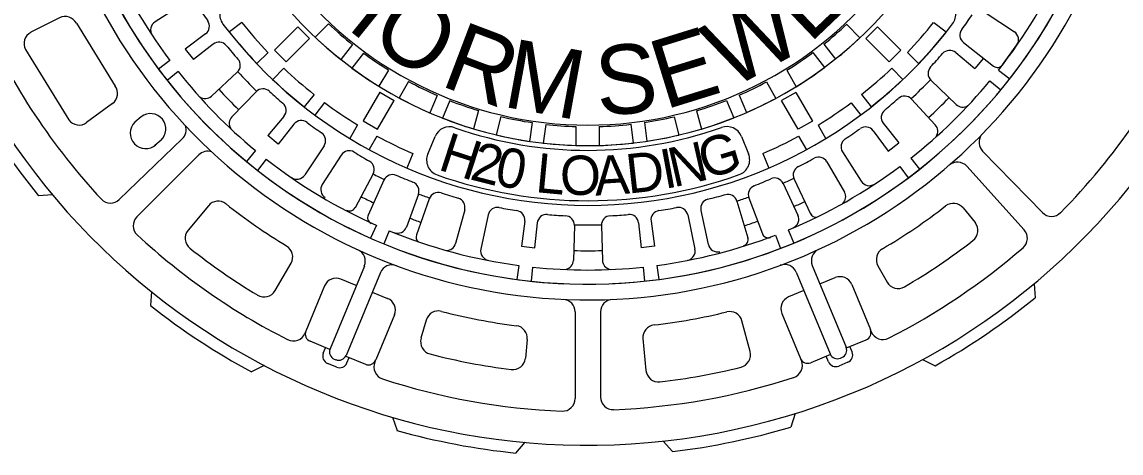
# Model space of a CAD drawing. Extents: x -7.1 to 10, y -5 to 6.
# Drawn here: x -5.508 to -3.691, y -0.443 to 0.27 of the extents above; entities that cross this region are included whole.
import ezdxf

# ---------------------------------------------------------------- set-up
doc = ezdxf.new("R2010")
doc.units = 0
doc.layers.add('Level 1', color=7, linetype='Continuous')

# ---------------------------------------------------------------- blocks, each defined once
blk = doc.blocks.new('CRAN')
at = {"layer": 'Level 1'}
for p, q in [((-3.652, 6.599), (-1.391, 7.083)), ((-3.232, 4.178), (-1.568, 4.4)), ((-1.568, 4.4), (-1.47, 3.52)), ((-3.114, 3.352), (-1.47, 3.52)), ((-2.949, 0.9), (-0.638, 0.965)), ((-2.949, -0.892), (-0.638, -0.957)), ((-3.114, -3.345), (-1.471, -3.52)), ((-1.568, -4.392), (-1.47, -3.512)), ((-3.232, -4.17), (-1.568, -4.392)), ((-3.652, -6.592), (-1.391, -7.076))]:
    blk.add_line(p, q, dxfattribs=at)
for centre, radius, start, end in [((-3.521, 5.988), 0.625, 102.07218, 190.93682), ((-1.26, 6.472), 0.625, 11.01435, 102.07218), ((-34.491, 0.004), 30.918, 8.74094, 10.93682), ((-3.315, 4.797), 0.625, 188.74094, 277.60558), ((-3.048, 2.731), 0.625, 96.07758, 184.94222), ((-34.473, 0.013), 30.918, 2.74634, 4.94222), ((-2.967, 1.524), 0.625, 182.74634, 271.61098), ((-0.656, 1.589), 0.625, 271.61098, 348.82418), ((-2.967, -1.517), 0.625, 88.38902, 177.25366), ((-0.656, -1.582), 0.625, 11.17582, 88.38902), ((-34.473, -0.006), 30.918, 355.05778, 357.25366), ((-3.048, -2.723), 0.625, 175.05778, 263.92242), ((-3.315, -4.79), 0.625, 82.39442, 171.25906), ((-34.491, 0.004), 30.918, 349.06318, 351.25906), ((-3.521, -5.981), 0.625, 169.06318, 257.92782), ((-1.26, -6.464), 0.625, 257.92782, 348.98565)]:
    blk.add_arc(centre, radius, start, end, dxfattribs=at)

msp = doc.modelspace()

# ---------------------------------------------------------------- linework, layer by layer
at = {"layer": 'Level 1'}
for p, q in [((-5.4455, 0.2769), (-5.4929, 0.2529)), ((-3.9159, 0.2859), (-3.8677, 0.2539)), ((-5.4177, 0.2681), (-5.3534, 0.164)), ((-5.1443, 0.2694), (-5.1649, 0.2535)), ((-5.0517, 0.2621), (-5.0903, 0.2235)), ((-5.0517, 0.2621), (-5.0323, 0.2428)), ((-5.001, 0.2668), (-5.0231, 0.2447)), ((-4.1447, 0.2661), (-4.1228, 0.2438)), ((-4.0936, 0.2621), (-4.113, 0.2428)), ((-4.0936, 0.2621), (-4.055, 0.2235)), ((-4.001, 0.2694), (-3.9804, 0.2535)), ((-5.071, 0.2041), (-5.0323, 0.2428)), ((-4.0743, 0.2041), (-4.113, 0.2428)), ((-5.5019, 0.2245), (-5.4301, 0.1082)), ((-5.101, 0.2196), (-5.1194, 0.2011)), ((-5.0903, 0.2235), (-5.071, 0.2041)), ((-4.9613, 0.2325), (-4.9804, 0.2077)), ((-4.9433, 0.2187), (-4.9624, 0.1939)), ((-4.2005, 0.2195), (-4.1815, 0.1947)), ((-4.1825, 0.2334), (-4.1635, 0.2086)), ((-4.055, 0.2235), (-4.0743, 0.2041)), ((-4.0443, 0.2196), (-4.0259, 0.2011)), ((-3.9645, 0.2195), (-3.9328, 0.1931)), ((-3.9518, 0.2361), (-3.9019, 0.197)), ((-3.8872, 0.1989), (-3.8635, 0.232)), ((-5.2633, 0.2062), (-5.2821, 0.1922)), ((-3.9188, 0.2102), (-3.9328, 0.1931)), ((-5.2493, 0.188), (-5.2677, 0.1735)), ((-5.0749, 0.1934), (-5.0933, 0.175)), ((-4.9019, 0.1906), (-4.9178, 0.1637)), ((-4.2439, 0.1901), (-4.2283, 0.163)), ((-4.0704, 0.1934), (-4.052, 0.175)), ((-3.8937, 0.1904), (-3.8753, 0.176)), ((-4.8686, 0.1714), (-4.8843, 0.1443)), ((-4.2772, 0.1709), (-4.2618, 0.1437)), ((-4.0055, 0.1737), (-3.9639, 0.1336)), ((-3.9082, 0.1725), (-3.8901, 0.1576)), ((-5.025, 0.1502), (-5.041, 0.1296)), ((-4.9164, 0.1538), (-4.9437, 0.1064)), ((-4.9164, 0.1538), (-4.8927, 0.1401)), ((-4.8214, 0.1485), (-4.8335, 0.1197)), ((-4.3222, 0.1491), (-4.3103, 0.1202)), ((-4.2287, 0.1535), (-4.2524, 0.1399)), ((-4.2287, 0.1535), (-4.2014, 0.1062)), ((-4.1203, 0.1502), (-4.1043, 0.1296)), ((-5.358, 0.1352), (-5.4007, 0.1036)), ((-5.0077, 0.1368), (-5.0235, 0.1161)), ((-4.92, 0.0927), (-4.8927, 0.1401)), ((-4.8005, 0.1399), (-4.8125, 0.111)), ((-4.3431, 0.1404), (-4.3313, 0.1115)), ((-4.2251, 0.0925), (-4.2524, 0.1399)), ((-4.1374, 0.1365), (-4.1216, 0.1158)), ((-4.0375, 0.1424), (-3.9983, 0.1)), ((-5.3107, 0.1133), (-5.3212, 0.1043)), ((-4.7532, 0.1235), (-4.7616, 0.0934)), ((-4.7161, 0.1135), (-4.7242, 0.0833)), ((-4.4298, 0.1133), (-4.422, 0.083)), ((-4.3927, 0.1232), (-4.3847, 0.093)), ((-4.9531, 0.0999), (-4.966, 0.0773)), ((-4.9437, 0.1064), (-4.92, 0.0927)), ((-4.6646, 0.1036), (-4.6688, 0.0726)), ((-4.6421, 0.1007), (-4.6462, 0.0697)), ((-4.5922, 0.0971), (-4.5925, 0.0658)), ((-4.5537, 0.0971), (-4.5538, 0.0658)), ((-4.5014, 0.1008), (-4.4975, 0.0698)), ((-4.479, 0.1038), (-4.4749, 0.0728)), ((-4.2014, 0.1062), (-4.2251, 0.0925)), ((-4.1921, 0.0996), (-4.1791, 0.077)), ((-4.0843, 0.1025), (-4.0587, 0.0701)), ((-5.2427, 0.0766), (-5.3468, -0.0238)), ((-5.2774, 0.0748), (-5.2879, 0.0658)), ((-4.921, 0.0814), (-4.9341, 0.0589)), ((-4.837, 0.0516), (-4.825, 0.0806)), ((-4.3187, 0.0809), (-4.3069, 0.0519)), ((-4.2242, 0.0811), (-4.2111, 0.0586)), ((-4.1011, 0.0902), (-4.076, 0.0566)), ((-5.1217, 0.0574), (-5.1367, 0.0394)), ((-4.1517, 0.0554), (-4.1209, 0.0065)), ((-4.076, 0.0566), (-4.0585, 0.0702)), ((-3.8212, -0.0452), (-3.9202, 0.0565)), ((-5.2154, 0.0501), (-5.3177, -0.0522)), ((-5.1038, 0.043), (-5.1183, 0.0246)), ((-4.9801, 0.0499), (-5.0114, 0.0014)), ((-4.8617, 0.0525), (-4.8717, 0.0285)), ((-4.2835, 0.0523), (-4.2735, 0.0283)), ((-4.1773, 0.0388), (-4.1485, -0.0113)), ((-4.0387, 0.045), (-4.0242, 0.0266)), ((-4.9271, 0.0187), (-4.9572, -0.0371)), ((-4.0569, 0.031), (-4.0429, 0.0122)), ((-3.9461, 0.0314), (-3.8514, -0.0736)), ((-4.9094, 0.0085), (-4.9356, -0.0492)), ((-4.2497, 0.003), (-4.2253, -0.0494)), ((-4.2317, 0.0102), (-4.2045, -0.047)), ((-5.4571, -0.0156), (-5.4804, -0.0173)), ((-4.8525, -0.0147), (-4.8723, -0.0691)), ((-5.1994, -0.0338), (-5.2332, -0.0745)), ((-4.8347, -0.0223), (-4.8558, -0.082)), ((-4.3261, -0.0261), (-4.3079, -0.0868)), ((-4.3064, -0.0208), (-4.2841, -0.0802)), ((-4.776, -0.0406), (-4.791, -0.0964)), ((-4.3856, -0.0415), (-4.3734, -0.098)), ((-3.9524, -0.0376), (-3.9326, -0.0618)), ((-4.922, -0.0662), (-4.9315, -0.0876)), ((-4.9009, -0.0752), (-4.9098, -0.0969)), ((-4.2625, -0.0825), (-4.2541, -0.1044)), ((-4.2412, -0.074), (-4.2322, -0.0956)), ((-5.0893, -0.1743), (-5.063, -0.1287)), ((-4.9418, -0.1336), (-4.9985, -0.2705)), ((-4.9153, -0.1445), (-4.9721, -0.2814)), ((-4.6866, -0.1326), (-4.6897, -0.1559)), ((-4.6638, -0.1354), (-4.6662, -0.1587)), ((-4.4812, -0.1354), (-4.4787, -0.1587)), ((-4.4584, -0.1326), (-4.4553, -0.1559)), ((-4.228, -0.1439), (-4.172, -0.279)), ((-4.2016, -0.1329), (-4.1456, -0.268)), ((-4.0932, -0.1331), (-4.078, -0.1604)), ((-4.9551, -0.1657), (-4.9804, -0.1553)), ((-4.189, -0.1633), (-4.1637, -0.1528)), ((-3.8351, -0.1629), (-3.8334, -0.1861)), ((-5.2938, -0.1759), (-5.2953, -0.1991)), ((-5.0076, -0.1665), (-5.0385, -0.2411)), ((-4.9287, -0.1767), (-4.9034, -0.1871)), ((-4.2154, -0.1742), (-4.2407, -0.1847)), ((-4.1365, -0.1641), (-4.1056, -0.2386)), ((-4.8921, -0.2144), (-4.923, -0.2889)), ((-4.5933, -0.2096), (-4.5933, -0.3528)), ((-4.5517, -0.2096), (-4.5517, -0.3503)), ((-4.252, -0.2119), (-4.2211, -0.2865)), ((-4.8396, -0.223), (-4.8482, -0.2531)), ((-4.3042, -0.2752), (-4.3179, -0.2243)), ((-5.0385, -0.2411), (-5.04, -0.2447)), ((-4.4815, -0.2537), (-4.4766, -0.3063)), ((-4.1051, -0.2401), (-4.1042, -0.2423)), ((-4.999, -0.2716), (-5.0315, -0.2581)), ((-5.0096, -0.2777), (-5.0059, -0.2687)), ((-4.6725, -0.2551), (-4.6757, -0.2862)), ((-4.1451, -0.2691), (-4.1126, -0.2557)), ((-4.1356, -0.2757), (-4.1394, -0.2667)), ((-4.9903, -0.288), (-4.9903, -0.288)), ((-4.9725, -0.2825), (-4.94, -0.296)), ((-4.9705, -0.2939), (-4.9668, -0.2849)), ((-4.9237, -0.2904), (-4.9246, -0.2925)), ((-4.2211, -0.2865), (-4.2196, -0.2901)), ((-4.1716, -0.2801), (-4.2041, -0.2935)), ((-4.1748, -0.2919), (-4.1785, -0.2829)), ((-4.1538, -0.2855), (-4.1539, -0.2855)), ((-4.0192, -0.2882), (-3.9983, -0.2984)), ((-5.1076, -0.298), (-5.1284, -0.3085)), ((-4.9875, -0.301), (-5.0026, -0.2947)), ((-4.1427, -0.2927), (-4.1578, -0.299)), ((-4.2298, -0.3777), (-4.2371, -0.3999)), ((-4.8954, -0.3836), (-4.8878, -0.4056)), ((-4.6766, -0.4251), (-4.6918, -0.4429)), ((-4.4478, -0.4231), (-4.4324, -0.4405))]:
    msp.add_line(p, q, dxfattribs=at)
for centre, radius, start, end in [((-4.5726, 0.7218), 1.1516, 195.0717, 189.1227), ((-4.5725, 0.7218), 0.8854, 184.6051, 245.3048), ((-4.5725, 0.7218), 0.8854, 184.6051, 354.3326), ((-4.5725, 0.7218), 0.8854, 272.6352, 354.3326), ((-4.5725, 0.7218), 0.9115, 188.0305, 347.6848), ((-4.5725, 0.7218), 0.862, 202.6056, 216.7344), ((-4.5725, 0.7218), 0.862, 321.9456, 336.078), ((-4.5725, 0.7218), 0.6224, 216.9847, 323.0153), ((-4.5725, 0.7218), 0.6562, 217.1874, 322.8126), ((-5.1547, 0.2823), 0.026, 125, 217.0904), ((-3.9905, 0.2825), 0.026, 322.9239, 55), ((-5.4361, 0.2583), 0.0208, 28.0611, 116.8565), ((-4.5726, 0.722), 0.7729, 323.0809, 325.2768), ((-4.5712, 0.7239), 1.0983, 204.3143, 222.8654), ((-4.5726, 0.7224), 0.7557, 217.0904, 322.9239), ((-4.5725, 0.7219), 0.7292, 218.362, 223.5455), ((-4.5725, 0.7218), 0.625, 226.7203, 231.5279), ((-4.5725, 0.7218), 0.625, 308.6043, 313.1939), ((-4.5728, 0.7219), 0.7292, 316.4545, 321.638), ((-3.9422, 0.2484), 0.0156, 143.0809, 231.9456), ((-4.573, 0.7263), 1.0983, 315.3646, 335.5685), ((-5.4835, 0.2343), 0.0208, 116.8565, 207.9663), ((-4.5725, 0.7219), 0.7552, 218.3392, 223.6005), ((-4.5725, 0.7218), 0.6563, 226.6317, 231.5646), ((-4.5725, 0.7218), 0.6563, 308.552, 313.2544), ((-4.5728, 0.7219), 0.7552, 316.3995, 321.6608), ((-3.8763, 0.2409), 0.0156, 325.3544, 56.4122), ((-4.5725, 0.7218), 0.625, 233.6043, 238.1939), ((-4.5725, 0.7218), 0.625, 301.7203, 306.5279), ((-3.9745, 0.2075), 0.0156, 50.4176, 139.2822), ((-4.5722, 0.7219), 0.7729, 317.0863, 319.2822), ((-4.5725, 0.7218), 0.862, 218.262, 230.418), ((-4.5725, 0.7218), 0.7875, 222.7158, 225.9774), ((-4.5727, 0.7221), 0.7292, 226.4702, 231.6538), ((-4.5725, 0.7218), 0.6563, 233.552, 238.2544), ((-4.5725, 0.7218), 0.6563, 301.6317, 306.5646), ((-4.5726, 0.7221), 0.7292, 308.3462, 313.5298), ((-3.9946, 0.185), 0.0156, 137.0863, 225.951), ((-3.8955, 0.2052), 0.0104, 231.9456, 322.6551), ((-5.3704, 0.152), 0.0208, 306.5465, 35.3378), ((-4.5727, 0.7221), 0.7552, 226.4152, 231.6765), ((-4.5725, 0.7218), 0.625, 241.7203, 246.5279), ((-4.5725, 0.7218), 0.625, 293.6043, 298.1939), ((-4.5726, 0.7221), 0.7552, 308.3235, 313.5848), ((-4.5725, 0.7218), 0.862, 308.262, 320.418), ((-4.5725, 0.7218), 0.7875, 312.7158, 315.9774), ((-4.5725, 0.7211), 1.1703, 209.3462, 219.1251), ((-4.5725, 0.7218), 0.8301, 222.7192, 225.9733), ((-4.049, 0.1318), 0.0156, 42.729, 131.5937), ((-4.5726, 0.7219), 0.7292, 233.362, 238.5455), ((-4.5725, 0.7218), 0.6563, 241.6317, 246.5646), ((-4.5725, 0.7218), 0.625, 248.6043, 253.1939), ((-4.5725, 0.7218), 0.625, 286.7203, 291.5279), ((-4.5725, 0.7218), 0.6563, 293.552, 298.2544), ((-4.5721, 0.7219), 0.7292, 301.4147, 306.5983), ((-4.5725, 0.7216), 0.7729, 309.3978, 311.5937), ((-4.5725, 0.7218), 0.8301, 312.7192, 315.9733), ((-3.9531, 0.1448), 0.0156, 225.951, 303.1642), ((-5.2953, 0.093), 0.0255, 311.5699, 126.9738), ((-4.5725, 0.7218), 0.6563, 248.552, 253.2544), ((-4.5725, 0.7218), 0.625, 256.7203, 261.5279), ((-4.5725, 0.7218), 0.625, 278.6043, 283.1939), ((-4.5725, 0.7218), 0.6563, 286.6317, 291.5646), ((-4.072, 0.1122), 0.0156, 129.3978, 218.2624), ((-5.4131, 0.1203), 0.0208, 215.392, 306.5465), ((-5.3032, 0.0861), 0.0255, 134.687, 311.5622), ((-5.2571, 0.0916), 0.0208, 313.9401, 20.0195), ((-4.801, 0.0706), 0.026, 70.6644, 157.5067), ((-4.5725, 0.7218), 0.6641, 250.6644, 289.4373), ((-4.5725, 0.7218), 0.625, 263.6043, 268.1939), ((-4.5725, 0.7218), 0.625, 271.7203, 276.5279), ((-4.3428, 0.071), 0.026, 22.2988, 109.4373), ((-4.5726, 0.722), 0.7729, 303.4032, 305.5991), ((-4.1136, 0.0809), 0.0156, 36.7344, 125.5991), ((-4.0098, 0.0894), 0.0156, 325.5158, 42.729), ((-4.5727, 0.722), 0.7292, 241.4702, 246.6538), ((-4.5725, 0.7218), 0.6563, 256.6317, 261.5646), ((-4.5725, 0.7218), 0.6563, 278.552, 283.2544), ((-4.572, 0.722), 0.7292, 293.3065, 298.49), ((-4.1385, 0.0637), 0.0156, 123.4032, 212.2678), ((-3.9053, 0.0711), 0.0208, 145.8214, 224.2281), ((-5.2007, 0.0354), 0.0208, 71.0549, 135), ((-4.9669, 0.0415), 0.0156, 58.3474, 147.2121), ((-4.5531, 0.7127), 0.7729, 238.3474, 240.5433), ((-4.5725, 0.7218), 0.6563, 263.552, 268.2544), ((-4.5725, 0.7218), 0.6563, 271.6317, 276.5646), ((-4.5725, 0.7218), 0.862, 231.9456, 246.078), ((-4.9409, 0.0261), 0.0156, 331.6787, 60.5433), ((-4.813, 0.0417), 0.026, 157.5067, 250.5275), ((-4.331, 0.0421), 0.026, 289.5614, 22.2988), ((-4.5708, 0.722), 0.7729, 296.6109, 298.8068), ((-4.1909, 0.031), 0.0156, 29.9422, 118.8068), ((-3.9615, 0.0174), 0.0208, 42.022, 131.4737), ((-4.5725, 0.7218), 0.7875, 243.2323, 244.7184), ((-4.5725, 0.7218), 0.862, 292.6056, 306.7344), ((-4.2176, 0.017), 0.0156, 116.6109, 205.4756), ((-4.9982, -0.0071), 0.0156, 147.2121, 238.2699), ((-4.8952, 0.002), 0.0156, 66.704, 155.5686), ((-4.5833, 0.7263), 0.7729, 246.704, 248.8998), ((-4.8672, -0.0094), 0.0156, 340.0352, 68.8998), ((-4.5725, 0.7218), 0.7474, 250.5275, 289.5614), ((-4.5834, 0.7173), 0.7729, 291.704, 293.8998), ((-4.2639, -0.0036), 0.0156, 25.0352, 113.8998), ((-4.5725, 0.7218), 0.7875, 294.1803, 295.5909), ((-4.1076, 0.0149), 0.0156, 212.2678, 303.3256), ((-4.5725, 0.7218), 0.7875, 249.1803, 250.5909), ((-4.8199, -0.0275), 0.0156, 71.6109, 160.4756), ((-4.5712, 0.7208), 0.7729, 251.6109, 253.8068), ((-4.5524, 0.7291), 0.7729, 283.3474, 285.5433), ((-4.3411, -0.0306), 0.0156, 16.6787, 105.5433), ((-4.2917, -0.0154), 0.0156, 111.704, 200.5686), ((-4.162, -0.0191), 0.0156, 315.2442, 29.9422), ((-5.3612, -0.0088), 0.0208, 222.8438, 313.9401), ((-5.1834, -0.0471), 0.0208, 51.5447, 140.3232), ((-4.5712, 0.7238), 0.9635, 231.5447, 238.807), ((-4.5725, 0.7218), 0.8301, 243.1524, 244.7577), ((-4.7911, -0.0365), 0.0156, 344.9422, 73.8068), ((-4.3704, -0.0382), 0.0156, 103.3474, 192.2121), ((-4.5725, 0.7218), 0.7875, 288.2323, 289.7184), ((-4.5725, 0.7218), 0.8301, 294.2248, 295.5852), ((-4.5729, 0.7262), 0.9635, 300.3841, 307.8801), ((-3.9685, -0.0507), 0.0208, 39.1639, 127.8801), ((-5.303, -0.067), 0.0208, 135, 227.2195), ((-4.9664, -0.0321), 0.0104, 240.9692, 331.6787), ((-4.9262, -0.0535), 0.0104, 155.5686, 246.2781), ((-4.5725, 0.7218), 0.8301, 249.2248, 250.5852), ((-4.2394, -0.056), 0.0156, 293.9774, 25.0352), ((-4.1951, -0.0425), 0.0104, 205.4756, 273.3766), ((-3.8062, -0.0307), 0.0208, 224.2281, 315.3646), ((-4.887, -0.0637), 0.0156, 248.9774, 340.0352), ((-4.5725, 0.7218), 0.7875, 268.3758, 271.6374), ((-4.5725, 0.7218), 0.8301, 288.1524, 289.7577), ((-3.9488, -0.0749), 0.0208, 307.9191, 39.1639), ((-4.5712, 0.7239), 1.0983, 227.2195, 243.0661), ((-5.2172, -0.0878), 0.0208, 140.3232, 231.5594), ((-4.5725, 0.7218), 0.862, 247.6056, 262.3944), ((-4.846, -0.0855), 0.0104, 160.4756, 228.3766), ((-4.5725, 0.7218), 0.862, 277.6056, 291.078), ((-4.3179, -0.0898), 0.0104, 285.9692, 16.6787), ((-4.2744, -0.0765), 0.0104, 200.5686, 291.2781), ((-3.8669, -0.0876), 0.0208, 310.9426, 42.022), ((-4.5743, 0.7221), 1.0548, 231.5594, 238.9682), ((-5.081, -0.1183), 0.0208, 330.0206, 58.807), ((-4.9611, -0.1256), 0.0208, 337.5, 65.3048), ((-4.572, 0.7207), 0.8845, 249.7003, 267.3328), ((-4.8061, -0.0923), 0.0156, 270.2442, 344.9422), ((-4.5725, 0.7218), 0.8301, 268.3792, 271.6333), ((-4.3581, -0.0947), 0.0156, 192.2121, 283.2699), ((-4.1823, -0.1249), 0.0208, 114.807, 202.5), ((-4.075, -0.1229), 0.0208, 120.3841, 209.1622), ((-4.573, 0.7263), 1.0983, 296.9323, 310.9426), ((-4.573, 0.7263), 1.0365, 300.3463, 307.9191), ((-4.8961, -0.1525), 0.0208, 69.7003, 157.5), ((-4.5725, 0.7218), 0.862, 263.922, 276.078), ((-4.2472, -0.1519), 0.0208, 22.5, 110.3605), ((-4.9884, -0.1745), 0.0208, 67.5, 157.5), ((-4.1557, -0.172), 0.0208, 22.5, 112.5), ((-4.0598, -0.1502), 0.0208, 209.1622, 300.3463), ((-5.1074, -0.1639), 0.0208, 238.9682, 330.0206), ((-4.5723, 0.7212), 1.1703, 231.8462, 241.6251), ((-4.9114, -0.2064), 0.0208, 337.5, 67.5), ((-4.6142, -0.2096), 0.0208, 0, 87.3648), ((-4.5308, -0.2096), 0.0208, 92.6352, 180), ((-4.2327, -0.2039), 0.0208, 112.5, 202.5), ((-4.5718, 0.7217), 1.1703, 299.3462, 309.1251), ((-4.8196, -0.2287), 0.0208, 75.3841, 164.1622), ((-4.5712, 0.7238), 0.9635, 255.3841, 262.8801), ((-4.5729, 0.7262), 0.9635, 276.5447, 283.807), ((-4.338, -0.2297), 0.0208, 15.0206, 103.807), ((-4.6932, -0.253), 0.0208, 354.1639, 82.8801), ((-4.4607, -0.2517), 0.0208, 96.5447, 185.3232), ((-5.0592, -0.2367), 0.0208, 243.0661, 337.5), ((-5.0265, -0.2461), 0.013, 157.5, 247.5), ((-4.8281, -0.2588), 0.0208, 164.1622, 255.3463), ((-4.1176, -0.2436), 0.013, 292.5, 22.5), ((-4.0849, -0.2343), 0.0208, 202.5, 296.9323), ((-4.9865, -0.2755), 0.013, 157.5, 247.4327), ((-4.1576, -0.273), 0.013, 292.5706, 22.5), ((-4.9976, -0.2827), 0.013, 157.5, 247.5), ((-4.5712, 0.7238), 1.0951, 247.4327, 247.5706), ((-4.9841, -0.2764), 0.013, 247.5706, 337.5), ((-4.935, -0.284), 0.013, 247.5, 337.5), ((-4.5712, 0.7238), 1.0365, 255.3463, 262.9191), ((-4.6964, -0.2841), 0.0208, 262.9191, 354.1639), ((-4.3244, -0.2806), 0.0208, 283.9682, 15.0206), ((-4.2388, -0.298), 0.0208, 288.0661, 22.5), ((-4.209, -0.2815), 0.013, 202.5, 292.5), ((-4.16, -0.274), 0.013, 202.5, 292.4327), ((-4.5729, 0.7262), 1.0951, 292.4327, 292.5706), ((-4.1477, -0.2807), 0.013, 292.5, 22.5), ((-4.9825, -0.2889), 0.013, 247.5, 337.5), ((-4.9053, -0.3005), 0.0208, 157.5, 251.9323), ((-4.4558, -0.3044), 0.0208, 185.3232, 276.5594), ((-4.5739, 0.7228), 1.0548, 276.5594, 283.9682), ((-4.1628, -0.287), 0.013, 202.5, 292.5), ((-4.5712, 0.7239), 1.0983, 251.9323, 267.7134), ((-4.573, 0.7263), 1.0983, 272.2423, 288.0661), ((-4.6142, -0.3528), 0.0208, 267.7134, 0), ((-4.5308, -0.3503), 0.0208, 180, 272.2423), ((-4.5721, 0.7213), 1.1703, 254.3462, 264.1251), ((-4.5719, 0.7215), 1.1703, 276.8462, 286.6251)]:
    msp.add_arc(centre, radius, start, end, dxfattribs=at)

# ---------------------------------------------------------------- block references
at = {"layer": 'Level 1', "xscale": 0.025}
for p, yscale, rotation in [((-5.189, 0.1193), 0.024999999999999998, -135.66), ((-4.5725, -0.1402), 0.025000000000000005, -90.00000000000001)]:
    msp.add_blockref('CRAN', p, dxfattribs=dict(at, yscale=yscale, rotation=rotation))

# ---------------------------------------------------------------- texts
at = {"layer": 'Level 1'}
for s, height, rotation, p in [('T', 0.1144, 321.156, (-4.9932, 0.2773)), ('E', 0.1144, 43.6991, (-4.2063, 0.233)), ('W', 0.1144, 29.0041, (-4.3371, 0.1572)), ('O', 0.1144, 329.108, (-4.9364, 0.2332)), ('R', 0.1144, 339.2395, (-4.8188, 0.1657)), ('E', 0.1144, 17.2263, (-4.4453, 0.1246)), ('M', 0.1144, 349.6504, (-4.7156, 0.1305)), ('S', 0.1144, 4.56, (-4.5556, 0.1146)), ('H', 0.0651, 341.9891, (-4.822, 0.0265)), ('G', 0.0651, 16.73, (-4.3783, 0.0094)), ('2', 0.0651, 345.8384, (-4.7694, 0.0102)), ('0', 0.0651, 349.03, (-4.7286, 0.0009)), ('D', 0.0651, 6.4015, (-4.5057, -0.014)), ('I', 0.0651, 10.5343, (-4.4458, -0.0063)), ('N', 0.0651, 12.82, (-4.4311, -0.0037)), ('L', 0.0651, 354.583, (-4.6605, -0.0112)), ('O', 0.0651, 1.3103, (-4.6178, -0.0168)), ('A', 0.0651, 3.7878, (-4.5599, -0.0173))]:
    msp.add_text(s, height=height, rotation=rotation, dxfattribs=at).set_placement(p)

doc.saveas('drawing.dxf')
